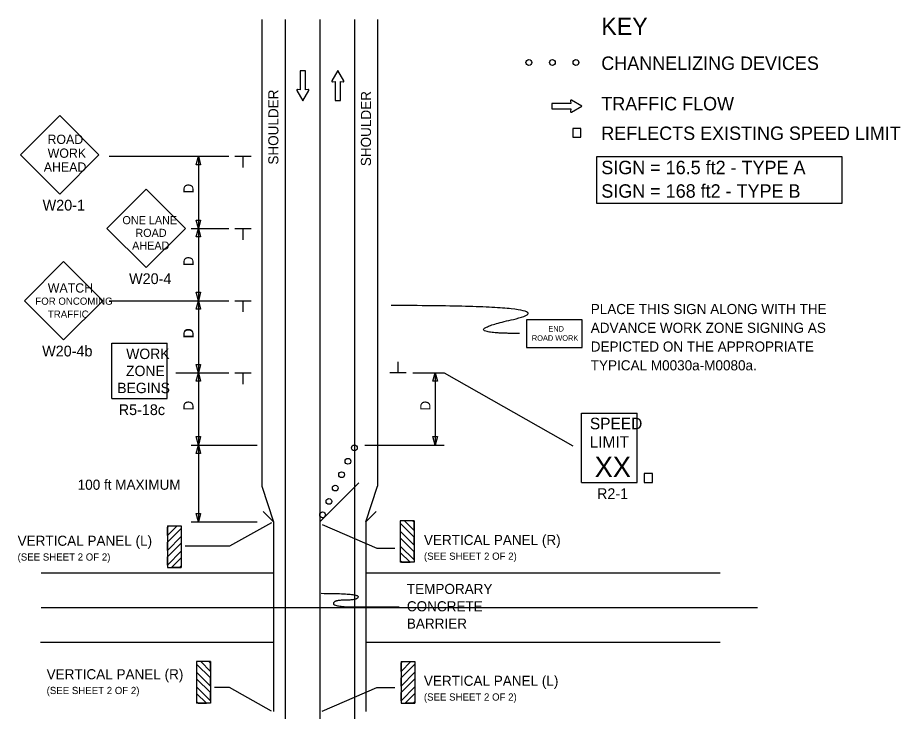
# Model space of a CAD drawing. Extents: x 16784 to 18475, y 7218 to 8259.
# Drawn here: x 16803 to 17414, y 7706 to 8187 of the extents above; entities that cross this region are included whole.
import ezdxf

# ---------------------------------------------------------------- set-up
doc = ezdxf.new("R2010")
doc.units = 0
for name, color, linetype in [('MT_SCRATCH_LEVEL_E', 7, 'Continuous'), ('PAVT_EDGE_EX', 7, 'Continuous'), ('TRAFFIC_SIGNS_PR', 7, 'Continuous'), ('TYPICAL_TEXT_DIMEN_EX', 7, 'Continuous'), ('TYPICAL_TEXT_DIMEN_PR', 7, 'Continuous')]:
    doc.layers.add(name, color=color, linetype=linetype)

msp = doc.modelspace()

# ---------------------------------------------------------------- linework, layer by layer
at = {"layer": 'MT_SCRATCH_LEVEL_E'}
for p, q in [((17002.27, 8150.09), (16998.52, 8150.09)), ((16998.52, 8150.09), (16998.52, 8136.83)), ((17002.27, 8150.09), (16998.52, 8150.09)), ((16998.52, 8150.09), (16998.52, 8136.83)), ((17002.27, 8136.83), (17002.27, 8150.09)), ((17002.27, 8136.83), (17002.27, 8150.09)), ((17024.66, 8150.35), (17020.55, 8143.11)), ((17024.66, 8150.35), (17020.55, 8143.11)), ((17028.81, 8143.11), (17024.66, 8150.35)), ((17028.81, 8143.11), (17024.66, 8150.35)), ((17021.03, 8142.43), (17022.81, 8142.74)), ((17021.03, 8142.43), (17022.81, 8142.74)), ((17022.81, 8142.74), (17022.81, 8129.49)), ((17022.81, 8142.74), (17022.81, 8129.49)), ((17026.55, 8129.49), (17026.55, 8142.74)), ((17026.55, 8142.74), (17028.33, 8142.43)), ((17026.55, 8129.49), (17026.55, 8142.74)), ((17026.55, 8142.74), (17028.33, 8142.43)), ((16996.27, 8136.47), (17000.41, 8129.22)), ((16996.27, 8136.47), (17000.41, 8129.22)), ((16998.52, 8136.83), (16996.75, 8137.15)), ((16998.52, 8136.83), (16996.75, 8137.15)), ((17000.41, 8129.22), (17004.53, 8136.47)), ((17000.41, 8129.22), (17004.53, 8136.47)), ((17004.04, 8137.15), (17002.27, 8136.83)), ((17004.04, 8137.15), (17002.27, 8136.83)), ((17022.81, 8129.49), (17026.55, 8129.49)), ((17022.81, 8129.49), (17026.55, 8129.49)), ((17185.65, 8129.19), (17185.97, 8127.41)), ((17185.65, 8129.19), (17185.97, 8127.41)), ((17193.57, 8125.56), (17186.33, 8129.67)), ((17193.57, 8125.56), (17186.33, 8129.67)), ((17185.97, 8127.41), (17172.71, 8127.41)), ((17172.71, 8127.41), (17172.71, 8123.67)), ((17185.97, 8127.41), (17172.71, 8127.41)), ((17172.71, 8127.41), (17172.71, 8123.67)), ((17172.71, 8123.67), (17185.97, 8123.67)), ((17172.71, 8123.67), (17185.97, 8123.67)), ((17185.97, 8123.67), (17185.65, 8121.89)), ((17185.97, 8123.67), (17185.65, 8121.89)), ((17186.33, 8121.41), (17193.57, 8125.56)), ((17186.33, 8121.41), (17193.57, 8125.56))]:
    msp.add_line(p, q, dxfattribs=at)
for centre, start, end in [((17020.95, 8142.89), 150.42484, 279.96381), ((17020.95, 8142.89), 150.42484, 279.96381), ((17028.4, 8142.89), 260.03619, 29.77312), ((17028.4, 8142.89), 260.03619, 29.77312), ((16996.68, 8136.69), 80.03619, 209.77312), ((16996.68, 8136.69), 80.03619, 209.77312), ((17004.12, 8136.69), 330.42484, 99.96381), ((17004.12, 8136.69), 330.42484, 99.96381), ((17186.11, 8129.26), 60.42484, 189.96381), ((17186.11, 8129.26), 60.42484, 189.96381), ((17186.11, 8121.82), 170.03619, 299.77312), ((17186.11, 8121.82), 170.03619, 299.77312)]:
    msp.add_arc(centre, 0.463, start, end, dxfattribs=at)
at = {"layer": 'PAVT_EDGE_EX'}
for p, q in [((16972.07, 8185.68), (16972.07, 7862.31)), ((16988.07, 8185.68), (16988.07, 7363.75)), ((17012.07, 8185.68), (17012.07, 7363.75)), ((17036.07, 8185.68), (17036.07, 7363.75)), ((17052.07, 8185.68), (17052.07, 7862.31)), ((16972.07, 7862.31), (16980.07, 7837.6)), ((17012.07, 7837.6), (17039.08, 7864.62)), ((17044.07, 7837.6), (17052.07, 7862.31)), ((16980.07, 7837.6), (16973, 7844.68)), ((17044.07, 7837.6), (17051.14, 7844.68)), ((16980.07, 7837.6), (16980.07, 7706.21)), ((17012.07, 7837.6), (17012.07, 7706.21)), ((17044.07, 7837.6), (17044.07, 7706.21)), ((16819.22, 7802.34), (16980.07, 7802.34)), ((16819.22, 7802.34), (16980.07, 7802.34)), ((17044.07, 7802.34), (17289.26, 7802.34)), ((16819.22, 7778.34), (17315.26, 7778.34)), ((16818.7, 7754.34), (16980.07, 7754.34)), ((17044.07, 7754.34), (17289.26, 7754.34))]:
    msp.add_line(p, q, dxfattribs=at)
for points in [[(17012.07, 8185.68), (17012.07, 8160.68)], [(17012.07, 8085.68), (17012.07, 8060.68)], [(17012.07, 7985.68), (17012.07, 7960.68)], [(17012.07, 7885.68), (17012.07, 7860.68)], [(16819.22, 7778.34), (16844.22, 7778.34)], [(16919.22, 7778.34), (16944.22, 7778.34)], [(17119.22, 7778.34), (17144.22, 7778.34)], [(17219.22, 7778.34), (17244.22, 7778.34)]]:
    msp.add_lwpolyline(points, dxfattribs=at)
at = {"layer": 'TRAFFIC_SIGNS_PR'}
for p, q in [((16832.09, 8119.01), (16804.94, 8091.86)), ((16859.24, 8091.86), (16832.09, 8119.01)), ((16804.94, 8091.86), (16832.09, 8064.7)), ((16832.09, 8064.7), (16859.24, 8091.86)), ((16891.93, 8068.07), (16864.78, 8040.92)), ((16919.08, 8040.92), (16891.93, 8068.07)), ((16864.78, 8040.92), (16891.93, 8013.77)), ((16891.93, 8013.77), (16919.08, 8040.92)), ((16834.77, 8017.94), (16807.62, 7990.79)), ((16861.92, 7990.79), (16834.77, 8017.94)), ((16807.62, 7990.79), (16834.77, 7963.64)), ((16834.77, 7963.64), (16861.92, 7990.79)), ((16868.12, 7923.01), (16868.12, 7961.41)), ((16868.12, 7961.41), (16906.52, 7961.41)), ((16906.52, 7923.01), (16906.52, 7961.41)), ((16868.12, 7923.01), (16906.52, 7923.01)), ((17193.38, 7912.88), (17231.78, 7912.88)), ((17193.38, 7864.88), (17193.38, 7912.88)), ((17231.78, 7864.88), (17231.78, 7912.88)), ((17193.38, 7864.88), (17231.78, 7864.88)), ((16906.63, 7834.79), (16916.23, 7834.79)), ((16906.63, 7834.79), (16906.63, 7805.99)), ((16906.63, 7833.71), (16907.71, 7834.79)), ((16906.63, 7828.05), (16913.37, 7834.79)), ((16916.23, 7834.79), (16916.23, 7805.99)), ((17077.5, 7838.39), (17067.9, 7838.39)), ((17067.9, 7838.39), (17067.9, 7809.59)), ((17077.5, 7827.12), (17067.9, 7836.72)), ((17077.5, 7831.64), (17070.76, 7838.39)), ((17077.5, 7837.3), (17076.42, 7838.39)), ((17077.5, 7838.39), (17077.5, 7809.59)), ((16906.63, 7823.52), (16916.23, 7833.12)), ((17077.5, 7821.46), (17067.9, 7831.06)), ((16906.63, 7817.87), (16916.23, 7827.47)), ((16906.63, 7813.34), (16916.23, 7822.94)), ((16908.04, 7824.94), (16909.46, 7826.35)), ((17077.5, 7816.93), (17067.9, 7826.53)), ((16906.63, 7807.68), (16916.23, 7817.28)), ((17077.5, 7811.28), (17067.9, 7820.88)), ((17074.67, 7809.59), (17067.9, 7816.35)), ((16909.46, 7805.99), (16916.23, 7812.76)), ((17069.01, 7809.59), (17067.9, 7810.69)), ((16906.63, 7805.99), (16916.23, 7805.99)), ((16915.12, 7805.99), (16916.23, 7807.1)), ((17077.5, 7809.59), (17067.9, 7809.59)), ((16936.47, 7740.81), (16926.87, 7740.81)), ((16926.87, 7740.81), (16926.87, 7712.01)), ((16936.47, 7729.54), (16926.87, 7739.14)), ((16936.47, 7734.06), (16929.73, 7740.81)), ((16936.47, 7739.72), (16935.39, 7740.81)), ((16936.47, 7740.81), (16936.47, 7712.01)), ((17068.37, 7740.81), (17077.97, 7740.81)), ((17068.37, 7740.81), (17068.37, 7712.01)), ((17068.37, 7739.72), (17069.46, 7740.81)), ((17068.37, 7734.06), (17075.12, 7740.81)), ((17068.37, 7729.54), (17077.97, 7739.14)), ((17077.97, 7740.81), (17077.97, 7712.01)), ((16936.47, 7723.88), (16926.87, 7733.48)), ((17068.37, 7723.88), (17077.97, 7733.48)), ((17069.79, 7730.95), (17071.2, 7732.36)), ((16936.47, 7719.35), (16926.87, 7728.95)), ((17068.37, 7719.35), (17077.97, 7728.95)), ((16936.47, 7713.7), (16926.87, 7723.3)), ((16933.64, 7712.01), (16926.87, 7718.77)), ((17068.37, 7713.7), (17077.97, 7723.3)), ((17071.21, 7712.01), (17077.97, 7718.77)), ((16927.98, 7712.01), (16926.87, 7713.11)), ((17076.87, 7712.01), (17077.97, 7713.11)), ((16936.47, 7712.01), (16926.87, 7712.01)), ((17068.37, 7712.01), (17077.97, 7712.01))]:
    msp.add_line(p, q, dxfattribs=at)
for points in [[(17187.22, 8103.98), (17192.82, 8103.98), (17192.82, 8110.15), (17187.22, 8110.15)], [(17155.35, 7958.27), (17193.75, 7958.27), (17193.75, 7977.47), (17155.35, 7977.47)], [(17236.8, 7864.88), (17242.39, 7864.88), (17242.39, 7871.05), (17236.8, 7871.05)], [(16907.71, 7834.79), (16913.37, 7834.79), (16906.63, 7828.05), (16906.63, 7833.71)], [(17077.5, 7827.12), (17067.9, 7836.72), (17067.9, 7831.06), (17077.5, 7821.46)], [(17076.42, 7838.39), (17070.76, 7838.39), (17077.5, 7831.64), (17077.5, 7837.3)], [(16906.63, 7823.52), (16916.23, 7833.12), (16916.23, 7827.47), (16906.63, 7817.87)], [(16906.63, 7813.34), (16916.23, 7822.94), (16916.23, 7817.28), (16906.63, 7807.68)], [(17077.5, 7816.93), (17067.9, 7826.53), (17067.9, 7820.88), (17077.5, 7811.28)], [(17067.9, 7816.35), (17067.9, 7810.69), (17069.01, 7809.59), (17074.67, 7809.59)], [(16916.23, 7812.76), (16916.23, 7807.1), (16915.12, 7805.99), (16909.46, 7805.99)], [(16936.47, 7729.54), (16926.87, 7739.14), (16926.87, 7733.48), (16936.47, 7723.88)], [(16935.39, 7740.81), (16929.73, 7740.81), (16936.47, 7734.06), (16936.47, 7739.72)], [(17069.46, 7740.81), (17075.12, 7740.81), (17068.37, 7734.06), (17068.37, 7739.72)], [(17068.37, 7729.54), (17077.97, 7739.14), (17077.97, 7733.48), (17068.37, 7723.88)], [(16936.47, 7719.35), (16926.87, 7728.95), (16926.87, 7723.3), (16936.47, 7713.7)], [(17068.37, 7719.35), (17077.97, 7728.95), (17077.97, 7723.3), (17068.37, 7713.7)], [(16926.87, 7718.77), (16926.87, 7713.11), (16927.98, 7712.01), (16933.64, 7712.01)], [(17077.97, 7718.77), (17077.97, 7713.11), (17076.87, 7712.01), (17071.21, 7712.01)]]:
    msp.add_lwpolyline(points, close=True, dxfattribs=at)
for centre in [(17156.9, 8155.81), (17173.2, 8155.81), (17189.5, 8155.81), (17036.07, 7888.82), (17031.67, 7879.55), (17027.27, 7870.29), (17022.87, 7861.03), (17018.47, 7851.76), (17014.07, 7842.5)]:
    msp.add_circle(centre, 2, dxfattribs=at)
msp.add_open_spline([(17150.44, 7968.1), (17103.21, 7968.1), (17188.23, 7987.44), (17061.55, 7987.44)], degree=2, dxfattribs=at)
at = {"layer": 'TYPICAL_TEXT_DIMEN_EX'}
msp.add_lwpolyline([(17204.02, 8090.66), (17373.68, 8090.66), (17373.68, 8058.11), (17204.02, 8058.11)], close=True, dxfattribs=at)
at = {"layer": 'TYPICAL_TEXT_DIMEN_PR'}
for p, q in [((16866.37, 8090.82), (16949.07, 8090.82)), ((16926.5, 8084.96), (16928.07, 8090.82)), ((16928.07, 8090.82), (16928.07, 8040.82)), ((16928.07, 8090.82), (16929.64, 8084.96)), ((16953.32, 8090.82), (16964.57, 8090.82)), ((16958.94, 8090.82), (16958.94, 8083.04)), ((16928.07, 8084.96), (16926.5, 8084.96)), ((16929.64, 8084.96), (16928.07, 8084.96)), ((16928.07, 8040.82), (16926.5, 8046.68)), ((16926.5, 8046.68), (16928.07, 8046.68)), ((16928.07, 8040.82), (16926.5, 8046.68)), ((16926.5, 8046.68), (16928.07, 8046.68)), ((16928.07, 8046.68), (16929.64, 8046.68)), ((16929.64, 8046.68), (16928.07, 8040.82)), ((16928.07, 8046.68), (16929.64, 8046.68)), ((16929.64, 8046.68), (16928.07, 8040.82)), ((16923.07, 8040.82), (16949.07, 8040.82)), ((16926.5, 8034.96), (16928.07, 8040.82)), ((16928.07, 8040.82), (16928.07, 7990.82)), ((16928.07, 8040.82), (16929.64, 8034.96)), ((16953.32, 8040.82), (16964.57, 8040.82)), ((16958.94, 8040.82), (16958.94, 8033.04)), ((16928.07, 8034.96), (16926.5, 8034.96)), ((16929.64, 8034.96), (16928.07, 8034.96)), ((16928.07, 7990.82), (16926.5, 7996.68)), ((16926.5, 7996.68), (16928.07, 7996.68)), ((16928.07, 7996.68), (16929.64, 7996.68)), ((16929.64, 7996.68), (16928.07, 7990.82)), ((16866.37, 7990.82), (16949.07, 7990.82)), ((16926.5, 7984.96), (16928.07, 7990.82)), ((16928.07, 7990.82), (16929.64, 7984.96)), ((16928.07, 7990.82), (16928.07, 7940.82)), ((16953.32, 7990.82), (16964.57, 7990.82)), ((16958.94, 7990.82), (16958.94, 7983.04)), ((16928.07, 7984.96), (16926.5, 7984.96)), ((16929.64, 7984.96), (16928.07, 7984.96)), ((16928.07, 7940.82), (16926.5, 7946.68)), ((16926.5, 7946.68), (16928.07, 7946.68)), ((16928.07, 7946.68), (16929.64, 7946.68)), ((16929.64, 7946.68), (16928.07, 7940.82)), ((17066.32, 7940.76), (17066.32, 7948.54)), ((16912.51, 7940.82), (16949.07, 7940.82)), ((16926.5, 7934.96), (16928.07, 7940.82)), ((16928.07, 7940.82), (16928.07, 7890.82)), ((16928.07, 7940.82), (16929.64, 7934.96)), ((16953.32, 7940.82), (16964.57, 7940.82)), ((16958.94, 7940.82), (16958.94, 7933.04)), ((17071.94, 7940.76), (17060.69, 7940.76)), ((17076.51, 7940.82), (17098.25, 7940.82)), ((17090.5, 7934.96), (17092.07, 7940.82)), ((17092.07, 7940.82), (17092.07, 7890.82)), ((17092.07, 7940.82), (17093.64, 7934.96)), ((17098.25, 7940.82), (17187.27, 7890.31)), ((16928.07, 7934.96), (16926.5, 7934.96)), ((16929.64, 7934.96), (16928.07, 7934.96)), ((17092.07, 7934.96), (17090.5, 7934.96)), ((17093.64, 7934.96), (17092.07, 7934.96)), ((16928.07, 7890.82), (16926.5, 7896.68)), ((16926.5, 7896.68), (16928.07, 7896.68)), ((16928.07, 7896.68), (16929.64, 7896.68)), ((16929.64, 7896.68), (16928.07, 7890.82)), ((17092.07, 7890.82), (17090.5, 7896.68)), ((17090.5, 7896.68), (17092.07, 7896.68)), ((17092.07, 7896.68), (17093.64, 7896.68)), ((17093.64, 7896.68), (17092.07, 7890.82)), ((16923.07, 7890.82), (16968.77, 7890.82)), ((16926.5, 7884.96), (16928.07, 7890.82)), ((16928.07, 7890.82), (16929.64, 7884.96)), ((16928.07, 7890.82), (16928.07, 7837.6)), ((17043.43, 7890.82), (17098.25, 7890.82)), ((16928.07, 7884.96), (16926.5, 7884.96)), ((16929.64, 7884.96), (16928.07, 7884.96)), ((16928.07, 7837.6), (16926.5, 7843.47)), ((16926.5, 7843.47), (16928.07, 7843.47)), ((16928.07, 7843.47), (16929.64, 7843.47)), ((16929.64, 7843.47), (16928.07, 7837.6)), ((16923.07, 7837.6), (16968.77, 7837.6)), ((16978.79, 7837.05), (16949.54, 7820.82)), ((17013.75, 7835.85), (17051.54, 7819.41)), ((16949.54, 7820.82), (16918.95, 7820.82)), ((17051.54, 7819.41), (17064.01, 7819.41)), ((16949.54, 7722.81), (16939.28, 7722.81)), ((16978.79, 7706.58), (16949.54, 7722.81)), ((17013.75, 7706.5), (17051.54, 7722.95)), ((17051.54, 7722.95), (17064.01, 7722.95))]:
    msp.add_line(p, q, dxfattribs=at)
msp.add_open_spline([(17013.19, 7788.11), (17038.77, 7788.11), (17038.77, 7783.4), (17021.56, 7783.4), (17021.56, 7778.69), (17054.56, 7778.69), (17067.02, 7778.69)], degree=2, dxfattribs=at)

# ---------------------------------------------------------------- texts
at = {"layer": 'TRAFFIC_SIGNS_PR'}
for s, height, p in [('ROAD', 6.4, (16823.63, 8099.39)), ('WORK', 6.4, (16823.74, 8089.79)), ('AHEAD', 6.4, (16821.05, 8080.19)), ('W20-1', 7.44, (16820.26, 8053.26)), ('ONE LANE', 5.6, (16875.51, 8043.79)), ('ROAD', 5.6, (16884.46, 8034.99)), ('AHEAD', 5.6, (16882.22, 8026.19)), ('W20-4', 7.44, (16880.11, 8002.33)), ('WATCH', 6.4, (16823.82, 7996.46)), ('FOR ONCOMING', 5, (16815.19, 7987.98)), ('PLACE THIS SIGN ALONG WITH THE', 7, (17199.72, 7981.54)), ('TRAFFIC', 5, (16823.88, 7978.98)), ('ADVANCE WORK ZONE SIGNING AS', 7, (17199.72, 7968.54)), ('END', 3.831, (17170.35, 7969.4)), ('ROAD WORK', 3.831, (17158.96, 7963.02)), ('W20-4b', 7.44, (16819.93, 7952.2)), ('WORK', 7.217, (16878.12, 7950.38)), ('DEPICTED ON THE APPROPRIATE', 7, (17199.72, 7955.54)), ('ZONE', 7.217, (16878, 7938.57)), ('TYPICAL M0030a-M0080a.', 7, (17199.72, 7942.54)), ('BEGINS', 7.217, (16871.93, 7926.76)), ('R5-18c', 7.44, (16872.93, 7911.57)), ('SPEED', 8, (17199.15, 7901.74)), ('LIMIT', 8, (17198.99, 7888.94)), ('XX', 14.031, (17202.49, 7868.64)), ('R2-1', 7.44, (17204.06, 7853.44))]:
    msp.add_text(s, height=height, dxfattribs=at).set_placement(p)
at = {"layer": 'TYPICAL_TEXT_DIMEN_EX'}
for s, height, p in [('KEY', 12, (17207.05, 8174.86)), ('CHANNELIZING DEVICES', 9.3, (17207.05, 8150.65)), ('TRAFFIC FLOW', 9.3, (17207.05, 8122.61)), ('REFLECTS EXISTING SPEED LIMIT', 9.3, (17207.05, 8102.14)), ('SIGN = 16.5 ft2 - TYPE A', 9.3, (17207.05, 8078.43)), ('SIGN = 168 ft2 - TYPE B', 9.3, (17207.05, 8062.13))]:
    msp.add_text(s, height=height, dxfattribs=at).set_placement(p)
at = {"layer": 'TYPICAL_TEXT_DIMEN_PR'}
for s, p in [('SHOULDER', (16983.49, 8085.06)), ('SHOULDER', (17047.6, 8083.98)), ('D', (16924.73, 8065.04)), ('D', (16924.73, 8014.7)), ('D', (16924.73, 7964.98)), ('D', (16924.73, 7964.7)), ('D', (16924.73, 7914.7)), ('D', (17088.73, 7914.7))]:
    msp.add_text(s, height=7, rotation=90, dxfattribs=at).set_placement(p)
for s, height, p in [('100 ft MAXIMUM', 7, (16844.52, 7859.85)), ('VERTICAL PANEL (L)', 7, (16802.93, 7821.03)), ('VERTICAL PANEL (R)', 7, (17084.25, 7821.59)), ('(SEE SHEET 2 OF 2)', 5, (17084.25, 7811.34)), ('(SEE SHEET 2 OF 2)', 5, (16802.93, 7810.78)), ('TEMPORARY', 7, (17072.42, 7787.65)), ('CONCRETE', 7, (17072.42, 7775.65)), ('BARRIER', 7, (17072.42, 7763.65)), ('VERTICAL PANEL (R)', 7, (16823.03, 7728.57)), ('VERTICAL PANEL (L)', 7, (17084.22, 7724.04)), ('(SEE SHEET 2 OF 2)', 5, (16823.03, 7718.32)), ('(SEE SHEET 2 OF 2)', 5, (17084.22, 7713.79))]:
    msp.add_text(s, height=height, dxfattribs=at).set_placement(p)

doc.saveas('drawing.dxf')
